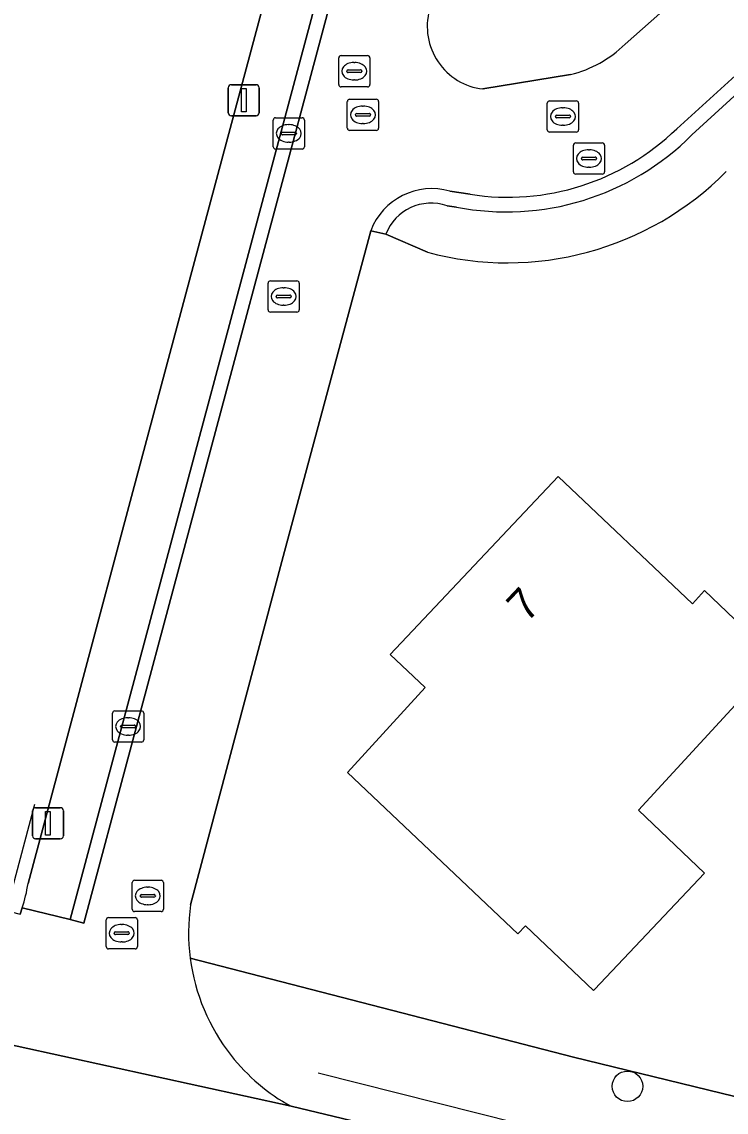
# Model space of a CAD drawing. Extents: x 162156 to 163172, y 378995 to 380779.
# Drawn here: x 162262.14 to 162284.71, y 380196.06 to 380230.97 of the extents above; entities that cross this region are included whole.
import ezdxf

# ---------------------------------------------------------------- set-up
doc = ezdxf.new("R2010")
doc.units = 0
for name, color, linetype in [('IMGEO_Boom', 7, 'Continuous'), ('IMGEO_Erf', 7, 'Continuous'), ('IMGEO_Groenvoorziening', 7, 'Continuous'), ('IMGEO_Hek', 7, 'Continuous'), ('IMGEO_Kolk', 7, 'Continuous'), ('IMGEO_Lichtmast', 7, 'Continuous'), ('IMGEO_Pand', 7, 'Continuous'), ('IMGEO_Pand_nummerreeks', 7, 'Continuous'), ('IMGEO_Rijbaan_lokaal_gesloten', 7, 'Continuous'), ('IMGEO_Rijbaan_lokaal_open', 7, 'Continuous'), ('IMGEO_Rioolput', 7, 'Continuous'), ('IMGEO_Voetpad_open', 7, 'Continuous')]:
    doc.layers.add(name, color=color, linetype=linetype)

msp = doc.modelspace()

# ---------------------------------------------------------------- linework, layer by layer
at = {"layer": 'IMGEO_Boom'}
msp.add_circle((162281.547, 380196.892), 0.489, dxfattribs=at)
at = {"layer": 'IMGEO_Erf'}
for points in [[(162262.339, 380203.383), (162265.702, 380215.938), (162271.428, 380237.285)], [(162275.136, 380223.595), (162273.804, 380224.174), (162273.322, 380224.284), (162270.517, 380213.853), (162267.546, 380202.699)], [(162211.037, 380224.077), (162212.191, 380221.758), (162209.83, 380220.583), (162210.565, 380216.608), (162210.488, 380216.162), (162210.385, 380215.565), (162210.605, 380215.503), (162210.69, 380216.294), (162234.408, 380210.305), (162248.758, 380206.096), (162250.906, 380205.466), (162256.032, 380203.963), (162260.463, 380202.82), (162262.082, 380202.403), (162262.154, 380202.611)], [(162267.536, 380200.996), (162279.818, 380197.828), (162298.313, 380193.322), (162299.663, 380189.615)]]:
    msp.add_lwpolyline(points, dxfattribs=at)
msp.add_lwpolyline([(162287.964, 380208.617), (162286.11, 380210.368), (162285.945, 380210.193), (162285.981, 380210.159), (162281.905, 380205.735), (162284.012, 380203.711), (162280.491, 380199.993), (162280.463, 380199.963), (162278.276, 380202.027), (162278.039, 380201.776), (162272.574, 380206.942), (162275.069, 380209.661), (162273.946, 380210.722), (162279.323, 380216.412), (162283.63, 380212.335), (162284.022, 380212.762), (162285.455, 380211.393), (162287.661, 380213.679), (162290.372, 380211.142)], close=True, dxfattribs=at)
for centre, radius, start, end in [((162277.699, 380233.132), 9.875, 254.9555, 315.2549), ((162257.442, 380204.148), 4.957, 341.9307, 351.1171), ((162273.872, 380201.81), 6.389, 172.004, 187.3231)]:
    msp.add_arc(centre, radius, start, end, dxfattribs=at)
at = {"layer": 'IMGEO_Groenvoorziening'}
for points in [[(162281.47, 380230.257), (162286.193, 380234.44), (162287.476, 380235.57)], [(162276.919, 380228.823), (162279.727, 380229.288)], [(162279.818, 380197.828), (162267.536, 380200.996)], [(162299.663, 380189.615), (162298.313, 380193.322), (162279.818, 380197.828)], [(162270.767, 380196.252), (162294.603, 380190.539), (162295.129, 380190.42)]]:
    msp.add_lwpolyline(points, dxfattribs=at)
for centre, radius, start, end in [((162277.142, 380230.82), 2.01, 164.6289, 263.6351), ((162278.84, 380232.936), 3.755, 283.6713, 314.4714), ((162273.835, 380201.814), 6.352, 187.395, 218.2953), ((162273.834, 380201.813), 6.351, 218.3011, 241.1244)]:
    msp.add_arc(centre, radius, start, end, dxfattribs=at)
at = {"layer": 'IMGEO_Hek'}
for points in [[(162261.779, 380202.993), (162262.552, 380205.925)], [(162325.53, 380205.107), (162316.565, 380198.358), (162306.984, 380191.725), (162299.257, 380191.374), (162294.601, 380191.534), (162271.637, 380197.316)]]:
    msp.add_lwpolyline(points, dxfattribs=at)
at = {"layer": 'IMGEO_Kolk'}
for p, q in [((162270.195, 380226.975), (162270.195, 380227.827)), ((162270.27, 380227.901), (162271.122, 380227.901)), ((162271.196, 380227.827), (162271.196, 380226.975)), ((162270.454, 380227.395), (162270.454, 380227.407)), ((162270.497, 380227.444), (162270.895, 380227.444)), ((162270.683, 380227.681), (162270.708, 380227.681)), ((162270.938, 380227.407), (162270.938, 380227.395)), ((162270.892, 380227.358), (162270.494, 380227.358)), ((162270.706, 380227.121), (162270.681, 380227.121)), ((162271.122, 380226.901), (162270.27, 380226.901)), ((162265.121, 380208.913), (162265.973, 380208.913)), ((162265.046, 380207.987), (162265.046, 380208.839)), ((162265.534, 380208.693), (162265.559, 380208.693)), ((162266.047, 380208.839), (162266.047, 380207.987)), ((162265.305, 380208.407), (162265.305, 380208.419)), ((162265.743, 380208.37), (162265.345, 380208.37)), ((162265.348, 380208.456), (162265.746, 380208.456)), ((162265.789, 380208.419), (162265.789, 380208.407)), ((162265.973, 380207.913), (162265.121, 380207.913)), ((162265.557, 380208.133), (162265.532, 380208.133))]:
    msp.add_line(p, q, dxfattribs=at)
for points in [[(162270.195, 380226.975), (162270.195, 380227.827)], [(162270.27, 380227.901), (162271.122, 380227.901)], [(162271.196, 380227.827), (162271.196, 380226.975)], [(162271.122, 380226.901), (162270.27, 380226.901)], [(162265.121, 380208.913), (162265.973, 380208.913)], [(162265.046, 380207.987), (162265.046, 380208.839)], [(162266.047, 380208.839), (162266.047, 380207.987)], [(162265.973, 380207.913), (162265.121, 380207.913)]]:
    msp.add_lwpolyline(points, dxfattribs=at)
for centre, radius, start, end in [((162270.272, 380227.825), 0.0765, 91.552, 178.448), ((162270.272, 380227.825), 0.0765, 91.552, 178.448), ((162271.12, 380227.825), 0.0765, 1.552, 88.448), ((162271.12, 380227.825), 0.0765, 1.552, 88.448), ((162270.494, 380227.404), 0.0403, 85.8775, 175.7526), ((162270.491, 380227.394), 0.0366, 178.938, 274.7102), ((162270.895, 380227.401), 0.043, 264.8664, 352.4533), ((162270.899, 380227.406), 0.0386, 1.7309, 96.639), ((162270.272, 380226.977), 0.0765, 181.552, 268.448), ((162270.272, 380226.977), 0.0765, 181.552, 268.448), ((162271.12, 380226.977), 0.0765, 271.552, 358.448), ((162271.12, 380226.977), 0.0765, 271.552, 358.448), ((162265.123, 380208.837), 0.0765, 91.552, 178.448), ((162265.123, 380208.837), 0.0765, 91.552, 178.448), ((162265.971, 380208.837), 0.0765, 1.552, 88.448), ((162265.971, 380208.837), 0.0765, 1.552, 88.448), ((162265.345, 380208.416), 0.0403, 85.8775, 175.7526), ((162265.342, 380208.406), 0.0366, 178.938, 274.7102), ((162265.746, 380208.413), 0.043, 264.8664, 352.4533), ((162265.75, 380208.418), 0.0386, 1.7309, 96.639), ((162265.123, 380207.989), 0.0765, 181.552, 268.448), ((162265.123, 380207.989), 0.0765, 181.552, 268.448), ((162265.971, 380207.989), 0.0765, 271.552, 358.448), ((162265.971, 380207.989), 0.0765, 271.552, 358.448)]:
    msp.add_arc(centre, radius, start, end, dxfattribs=at)
for centre, major_axis, ratio, start_param, end_param in [((162270.682, 380227.401), (-0.387, 0.002), 0.722429, 4.712389, 7.853982), ((162270.707, 380227.401), (-0.39, 0.002), 0.717154, 1.570796, 4.712389), ((162265.533, 380208.413), (-0.387, 0.002), 0.722429, 4.712389, 7.853982), ((162265.558, 380208.413), (-0.39, 0.002), 0.717154, 1.570796, 4.712389)]:
    msp.add_ellipse(centre, major_axis=major_axis, ratio=ratio, start_param=start_param, end_param=end_param, dxfattribs=at)
at = {"layer": 'IMGEO_Lichtmast'}
for p, q in [((162268.757, 380228.061), (162268.757, 380228.861)), ((162268.757, 380228.861), (162268.757, 380228.061)), ((162268.857, 380228.961), (162269.647, 380228.961)), ((162269.647, 380228.961), (162268.857, 380228.961)), ((162269.747, 380228.861), (162269.747, 380228.061)), ((162269.747, 380228.061), (162269.747, 380228.861)), ((162269.647, 380227.961), (162268.857, 380227.961)), ((162268.857, 380227.961), (162269.647, 380227.961)), ((162262.582, 380205.813), (162263.372, 380205.813)), ((162263.372, 380205.813), (162262.582, 380205.813)), ((162262.482, 380204.913), (162262.482, 380205.713)), ((162262.482, 380205.713), (162262.482, 380204.913)), ((162263.472, 380205.713), (162263.472, 380204.913)), ((162263.472, 380204.913), (162263.472, 380205.713)), ((162263.372, 380204.813), (162262.582, 380204.813)), ((162262.582, 380204.813), (162263.372, 380204.813))]:
    msp.add_line(p, q, dxfattribs=at)
for points in [[(162269.177, 380228.836), (162269.327, 380228.836), (162269.327, 380228.086), (162269.177, 380228.086), (162269.177, 380228.836)], [(162262.902, 380205.688), (162263.052, 380205.688), (162263.052, 380204.938), (162262.902, 380204.938), (162262.902, 380205.688)]]:
    msp.add_lwpolyline(points, dxfattribs=at)
for centre, start, end in [((162268.857, 380228.861), 90, 180), ((162268.857, 380228.861), 90, 180), ((162269.647, 380228.861), 0, 90), ((162269.647, 380228.861), 360, 90), ((162268.857, 380228.061), 180, 270), ((162268.857, 380228.061), 180, 270), ((162269.647, 380228.061), 270, 0), ((162269.647, 380228.061), 270, 0), ((162262.582, 380205.713), 90, 180), ((162262.582, 380205.713), 90, 180), ((162263.372, 380205.713), 0, 90), ((162263.372, 380205.713), 360, 90), ((162262.582, 380204.913), 180, 270), ((162262.582, 380204.913), 180, 270), ((162263.372, 380204.913), 270, 0), ((162263.372, 380204.913), 270, 0)]:
    msp.add_arc(centre, 0.1, start, end, dxfattribs=at)
at = {"layer": 'IMGEO_Pand'}
msp.add_lwpolyline([(162285.981, 380210.159), (162285.945, 380210.193), (162286.11, 380210.368), (162287.964, 380208.617), (162290.372, 380211.142), (162287.661, 380213.679), (162285.455, 380211.393), (162284.022, 380212.762), (162283.63, 380212.335), (162279.323, 380216.412), (162273.946, 380210.722), (162275.069, 380209.661), (162272.574, 380206.942), (162278.039, 380201.776), (162278.276, 380202.027), (162280.463, 380199.963), (162280.491, 380199.993), (162284.012, 380203.711), (162281.905, 380205.735)], close=True, dxfattribs=at)
at = {"layer": 'IMGEO_Rijbaan_lokaal_gesloten'}
msp.add_lwpolyline([(162295.129, 380190.42), (162294.603, 380190.539), (162270.767, 380196.252), (162257.586, 380199.133), (162242.127, 380202.849), (162211.76, 380210.925), (162209.697, 380211.57), (162201.813, 380214.036), (162199.997, 380214.604), (162197.517, 380215.45), (162195.952, 380211.32), (162198.831, 380210.194)], dxfattribs=at)
at = {"layer": 'IMGEO_Rijbaan_lokaal_open'}
for points in [[(162273.297, 380236.316), (162264.125, 380202.118), (162263.688, 380202.236), (162262.154, 380202.611), (162262.082, 380202.403)], [(162272.776, 380236.155), (162263.688, 380202.236), (162264.125, 380202.118), (162273.297, 380236.316)], [(162287.476, 380235.57), (162286.193, 380234.44), (162281.47, 380230.257)], [(162289.001, 380232.898), (162283.128, 380227.55)], [(162283.128, 380227.55), (162289.001, 380232.898)], [(162283.613, 380227.351), (162289.253, 380232.511)], [(162279.727, 380229.288), (162276.919, 380228.823)], [(162276.51, 380225.45), (162275.86, 380225.548)], [(162275.86, 380225.548), (162276.51, 380225.45)], [(162275.766, 380225.078), (162276.065, 380225.04)], [(162267.546, 380202.699), (162270.517, 380213.853), (162273.322, 380224.284)], [(162273.322, 380224.284), (162273.804, 380224.174)], [(162257.586, 380199.133), (162270.767, 380196.252)]]:
    msp.add_lwpolyline(points, dxfattribs=at)
for centre, radius, start, end in [((162277.142, 380230.82), 2.01, 164.6289, 263.6351), ((162278.84, 380232.936), 3.755, 283.6713, 314.4714), ((162277.71, 380233.145), 7.788, 261.1333, 314.0769), ((162277.71, 380233.145), 7.788, 261.1333, 314.0769), ((162277.664, 380233.299), 8.412, 259.0404, 315.006), ((162275.273, 380223.547), 2.085, 73.6476, 159.3018), ((162275.273, 380223.547), 2.085, 73.6476, 159.3018), ((162275.249, 380223.619), 1.548, 70.474, 159.0022), ((162273.872, 380201.81), 6.389, 172.004, 187.3231), ((162273.835, 380201.814), 6.352, 187.395, 218.2953), ((162273.834, 380201.813), 6.351, 218.3011, 241.1244)]:
    msp.add_arc(centre, radius, start, end, dxfattribs=at)
at = {"layer": 'IMGEO_Rioolput'}
for p, q in [((162272.369, 380229.891), (162273.221, 380229.891)), ((162272.294, 380228.965), (162272.294, 380229.817)), ((162272.782, 380229.671), (162272.807, 380229.671)), ((162273.295, 380229.817), (162273.295, 380228.965)), ((162272.553, 380229.385), (162272.553, 380229.397)), ((162272.991, 380229.348), (162272.593, 380229.348)), ((162272.596, 380229.434), (162272.994, 380229.434)), ((162273.037, 380229.397), (162273.037, 380229.385)), ((162273.221, 380228.891), (162272.369, 380228.891)), ((162272.805, 380229.111), (162272.78, 380229.111)), ((162272.646, 380228.496), (162273.498, 380228.496)), ((162272.571, 380227.57), (162272.571, 380228.422)), ((162273.059, 380228.276), (162273.084, 380228.276)), ((162273.572, 380228.422), (162273.572, 380227.57)), ((162278.98, 380227.515), (162278.98, 380228.367)), ((162279.055, 380228.441), (162279.907, 380228.441)), ((162279.468, 380228.221), (162279.493, 380228.221)), ((162279.981, 380228.367), (162279.981, 380227.515)), ((162272.83, 380227.99), (162272.83, 380228.002)), ((162273.268, 380227.953), (162272.87, 380227.953)), ((162272.873, 380228.039), (162273.271, 380228.039)), ((162273.314, 380228.002), (162273.314, 380227.99)), ((162279.239, 380227.935), (162279.239, 380227.947)), ((162279.677, 380227.898), (162279.279, 380227.898)), ((162279.282, 380227.984), (162279.68, 380227.984)), ((162279.723, 380227.947), (162279.723, 380227.935)), ((162273.498, 380227.496), (162272.646, 380227.496)), ((162273.082, 380227.716), (162273.057, 380227.716)), ((162279.907, 380227.441), (162279.055, 380227.441)), ((162279.491, 380227.661), (162279.466, 380227.661)), ((162279.89, 380227.096), (162280.742, 380227.096)), ((162279.815, 380226.17), (162279.815, 380227.022)), ((162280.303, 380226.876), (162280.328, 380226.876)), ((162280.816, 380227.022), (162280.816, 380226.17)), ((162280.074, 380226.59), (162280.074, 380226.602)), ((162280.512, 380226.553), (162280.114, 380226.553)), ((162280.117, 380226.639), (162280.515, 380226.639)), ((162280.558, 380226.602), (162280.558, 380226.59)), ((162280.742, 380226.096), (162279.89, 380226.096)), ((162280.326, 380226.316), (162280.301, 380226.316)), ((162270.03, 380221.754), (162270.03, 380222.606)), ((162270.105, 380222.68), (162270.957, 380222.68)), ((162271.031, 380222.606), (162271.031, 380221.754)), ((162270.289, 380222.174), (162270.289, 380222.186)), ((162270.332, 380222.223), (162270.73, 380222.223)), ((162270.518, 380222.46), (162270.543, 380222.46)), ((162270.773, 380222.186), (162270.773, 380222.174)), ((162270.727, 380222.137), (162270.329, 380222.137)), ((162270.541, 380221.9), (162270.516, 380221.9)), ((162270.957, 380221.68), (162270.105, 380221.68)), ((162265.676, 380202.561), (162265.676, 380203.413)), ((162265.751, 380203.487), (162266.603, 380203.487)), ((162266.677, 380203.413), (162266.677, 380202.561)), ((162265.935, 380202.981), (162265.935, 380202.993)), ((162265.978, 380203.03), (162266.376, 380203.03)), ((162266.164, 380203.267), (162266.189, 380203.267)), ((162266.419, 380202.993), (162266.419, 380202.981)), ((162266.373, 380202.944), (162265.975, 380202.944)), ((162266.187, 380202.707), (162266.162, 380202.707)), ((162264.917, 380202.293), (162265.769, 380202.293)), ((162266.603, 380202.487), (162265.751, 380202.487)), ((162264.842, 380201.367), (162264.842, 380202.219)), ((162265.33, 380202.073), (162265.355, 380202.073)), ((162265.843, 380202.219), (162265.843, 380201.367)), ((162265.101, 380201.787), (162265.101, 380201.799)), ((162265.539, 380201.75), (162265.141, 380201.75)), ((162265.144, 380201.836), (162265.542, 380201.836)), ((162265.585, 380201.799), (162265.585, 380201.787)), ((162265.769, 380201.293), (162264.917, 380201.293)), ((162265.353, 380201.513), (162265.328, 380201.513))]:
    msp.add_line(p, q, dxfattribs=at)
for points in [[(162272.369, 380229.891), (162273.221, 380229.891)], [(162272.294, 380228.965), (162272.294, 380229.817)], [(162273.295, 380229.817), (162273.295, 380228.965)], [(162273.221, 380228.891), (162272.369, 380228.891)], [(162272.646, 380228.496), (162273.498, 380228.496)], [(162272.571, 380227.57), (162272.571, 380228.422)], [(162273.572, 380228.422), (162273.572, 380227.57)], [(162278.98, 380227.515), (162278.98, 380228.367)], [(162279.055, 380228.441), (162279.907, 380228.441)], [(162279.981, 380228.367), (162279.981, 380227.515)], [(162273.498, 380227.496), (162272.646, 380227.496)], [(162279.907, 380227.441), (162279.055, 380227.441)], [(162279.89, 380227.096), (162280.742, 380227.096)], [(162279.815, 380226.17), (162279.815, 380227.022)], [(162280.816, 380227.022), (162280.816, 380226.17)], [(162280.742, 380226.096), (162279.89, 380226.096)], [(162270.03, 380221.754), (162270.03, 380222.606)], [(162270.105, 380222.68), (162270.957, 380222.68)], [(162271.031, 380222.606), (162271.031, 380221.754)], [(162270.957, 380221.68), (162270.105, 380221.68)], [(162265.676, 380202.561), (162265.676, 380203.413)], [(162265.751, 380203.487), (162266.603, 380203.487)], [(162266.677, 380203.413), (162266.677, 380202.561)], [(162264.917, 380202.293), (162265.769, 380202.293)], [(162266.603, 380202.487), (162265.751, 380202.487)], [(162264.842, 380201.367), (162264.842, 380202.219)], [(162265.843, 380202.219), (162265.843, 380201.367)], [(162265.769, 380201.293), (162264.917, 380201.293)]]:
    msp.add_lwpolyline(points, dxfattribs=at)
for centre, radius, start, end in [((162272.371, 380229.815), 0.0765, 91.552, 178.448), ((162272.371, 380229.815), 0.0765, 91.552, 178.448), ((162273.219, 380229.815), 0.0765, 1.552, 88.448), ((162273.219, 380229.815), 0.0765, 1.552, 88.448), ((162272.593, 380229.394), 0.0403, 85.8775, 175.7526), ((162272.59, 380229.384), 0.0366, 178.938, 274.7102), ((162272.994, 380229.391), 0.043, 264.8664, 352.4533), ((162272.998, 380229.396), 0.0386, 1.7309, 96.639), ((162272.371, 380228.967), 0.0765, 181.552, 268.448), ((162272.371, 380228.967), 0.0765, 181.552, 268.448), ((162273.219, 380228.967), 0.0765, 271.552, 358.448), ((162273.219, 380228.967), 0.0765, 271.552, 358.448), ((162272.648, 380228.42), 0.0765, 91.552, 178.448), ((162272.648, 380228.42), 0.0765, 91.552, 178.448), ((162273.496, 380228.42), 0.0765, 1.552, 88.448), ((162273.496, 380228.42), 0.0765, 1.552, 88.448), ((162279.057, 380228.365), 0.0765, 91.552, 178.448), ((162279.057, 380228.365), 0.0765, 91.552, 178.448), ((162279.905, 380228.365), 0.0765, 1.552, 88.448), ((162279.905, 380228.365), 0.0765, 1.552, 88.448), ((162272.87, 380227.999), 0.0403, 85.8775, 175.7526), ((162272.867, 380227.989), 0.0366, 178.938, 274.7102), ((162273.271, 380227.996), 0.043, 264.8664, 352.4533), ((162273.275, 380228.001), 0.0386, 1.7309, 96.639), ((162279.279, 380227.944), 0.0403, 85.8775, 175.7526), ((162279.276, 380227.934), 0.0366, 178.938, 274.7102), ((162279.68, 380227.941), 0.043, 264.8664, 352.4533), ((162279.684, 380227.946), 0.0386, 1.7309, 96.639), ((162272.648, 380227.572), 0.0765, 181.552, 268.448), ((162272.648, 380227.572), 0.0765, 181.552, 268.448), ((162273.496, 380227.572), 0.0765, 271.552, 358.448), ((162273.496, 380227.572), 0.0765, 271.552, 358.448), ((162279.057, 380227.517), 0.0765, 181.552, 268.448), ((162279.057, 380227.517), 0.0765, 181.552, 268.448), ((162279.905, 380227.517), 0.0765, 271.552, 358.448), ((162279.905, 380227.517), 0.0765, 271.552, 358.448), ((162279.892, 380227.02), 0.0765, 91.552, 178.448), ((162279.892, 380227.02), 0.0765, 91.552, 178.448), ((162280.74, 380227.02), 0.0765, 1.552, 88.448), ((162280.74, 380227.02), 0.0765, 1.552, 88.448), ((162280.114, 380226.599), 0.0403, 85.8775, 175.7526), ((162280.111, 380226.589), 0.0366, 178.938, 274.7102), ((162280.515, 380226.596), 0.043, 264.8664, 352.4533), ((162280.519, 380226.601), 0.0386, 1.7309, 96.639), ((162279.892, 380226.172), 0.0765, 181.552, 268.448), ((162279.892, 380226.172), 0.0765, 181.552, 268.448), ((162280.74, 380226.172), 0.0765, 271.552, 358.448), ((162280.74, 380226.172), 0.0765, 271.552, 358.448), ((162270.107, 380222.604), 0.0765, 91.552, 178.448), ((162270.107, 380222.604), 0.0765, 91.552, 178.448), ((162270.955, 380222.604), 0.0765, 1.552, 88.448), ((162270.955, 380222.604), 0.0765, 1.552, 88.448), ((162270.329, 380222.183), 0.0403, 85.8775, 175.7526), ((162270.326, 380222.173), 0.0366, 178.938, 274.7102), ((162270.73, 380222.18), 0.043, 264.8664, 352.4533), ((162270.734, 380222.185), 0.0386, 1.7309, 96.639), ((162270.107, 380221.756), 0.0765, 181.552, 268.448), ((162270.107, 380221.756), 0.0765, 181.552, 268.448), ((162270.955, 380221.756), 0.0765, 271.552, 358.448), ((162270.955, 380221.756), 0.0765, 271.552, 358.448), ((162265.753, 380203.411), 0.0765, 91.552, 178.448), ((162265.753, 380203.411), 0.0765, 91.552, 178.448), ((162266.601, 380203.411), 0.0765, 1.552, 88.448), ((162266.601, 380203.411), 0.0765, 1.552, 88.448), ((162265.975, 380202.99), 0.0403, 85.8775, 175.7526), ((162265.972, 380202.98), 0.0366, 178.938, 274.7102), ((162266.376, 380202.987), 0.043, 264.8664, 352.4533), ((162266.38, 380202.992), 0.0386, 1.7309, 96.639), ((162264.919, 380202.217), 0.0765, 91.552, 178.448), ((162264.919, 380202.217), 0.0765, 91.552, 178.448), ((162265.753, 380202.563), 0.0765, 181.552, 268.448), ((162265.753, 380202.563), 0.0765, 181.552, 268.448), ((162265.767, 380202.217), 0.0765, 1.552, 88.448), ((162265.767, 380202.217), 0.0765, 1.552, 88.448), ((162266.601, 380202.563), 0.0765, 271.552, 358.448), ((162266.601, 380202.563), 0.0765, 271.552, 358.448), ((162265.141, 380201.796), 0.0403, 85.8775, 175.7526), ((162265.138, 380201.786), 0.0366, 178.938, 274.7102), ((162265.542, 380201.793), 0.043, 264.8664, 352.4533), ((162265.546, 380201.798), 0.0386, 1.7309, 96.639), ((162264.919, 380201.369), 0.0765, 181.552, 268.448), ((162264.919, 380201.369), 0.0765, 181.552, 268.448), ((162265.767, 380201.369), 0.0765, 271.552, 358.448), ((162265.767, 380201.369), 0.0765, 271.552, 358.448)]:
    msp.add_arc(centre, radius, start, end, dxfattribs=at)
for centre, major_axis, ratio, start_param, end_param in [((162272.781, 380229.391), (-0.387, 0.002), 0.722429, 4.712389, 7.853982), ((162272.806, 380229.391), (-0.39, 0.002), 0.717154, 1.570796, 4.712389), ((162273.058, 380227.996), (-0.387, 0.002), 0.722429, 4.712389, 7.853982), ((162273.083, 380227.996), (-0.39, 0.002), 0.717154, 1.570796, 4.712389), ((162279.467, 380227.941), (-0.387, 0.002), 0.722429, 4.712389, 7.853982), ((162279.492, 380227.941), (-0.39, 0.002), 0.717154, 1.570796, 4.712389), ((162280.302, 380226.596), (-0.387, 0.002), 0.722429, 4.712389, 7.853982), ((162280.327, 380226.596), (-0.39, 0.002), 0.717154, 1.570796, 4.712389), ((162270.517, 380222.18), (-0.387, 0.002), 0.722429, 4.712389, 7.853982), ((162270.542, 380222.18), (-0.39, 0.002), 0.717154, 1.570796, 4.712389), ((162266.163, 380202.987), (-0.387, 0.002), 0.722429, 4.712389, 7.853982), ((162266.188, 380202.987), (-0.39, 0.002), 0.717154, 1.570796, 4.712389), ((162265.329, 380201.793), (-0.387, 0.002), 0.722429, 4.712389, 7.853982), ((162265.354, 380201.793), (-0.39, 0.002), 0.717154, 1.570796, 4.712389)]:
    msp.add_ellipse(centre, major_axis=major_axis, ratio=ratio, start_param=start_param, end_param=end_param, dxfattribs=at)
at = {"layer": 'IMGEO_Voetpad_open'}
for points in [[(162271.428, 380237.285), (162265.702, 380215.938), (162262.339, 380203.383)], [(162262.154, 380202.611), (162263.688, 380202.236), (162272.776, 380236.155)], [(162289.253, 380232.511), (162283.613, 380227.351)], [(162276.065, 380225.04), (162275.766, 380225.078)], [(162273.804, 380224.174), (162275.136, 380223.595)]]:
    msp.add_lwpolyline(points, dxfattribs=at)
for centre, radius, start, end in [((162277.664, 380233.299), 8.412, 259.0404, 315.006), ((162277.699, 380233.132), 9.875, 254.9555, 315.2549), ((162275.249, 380223.619), 1.548, 70.474, 159.0022), ((162257.442, 380204.148), 4.957, 341.9307, 351.1171)]:
    msp.add_arc(centre, radius, start, end, dxfattribs=at)

# ---------------------------------------------------------------- texts
at = {"layer": 'IMGEO_Pand_nummerreeks'}
msp.add_text('7', height=1, rotation=46.6216, dxfattribs=at).set_placement((162278.32, 380211.711))

doc.saveas('drawing.dxf')
